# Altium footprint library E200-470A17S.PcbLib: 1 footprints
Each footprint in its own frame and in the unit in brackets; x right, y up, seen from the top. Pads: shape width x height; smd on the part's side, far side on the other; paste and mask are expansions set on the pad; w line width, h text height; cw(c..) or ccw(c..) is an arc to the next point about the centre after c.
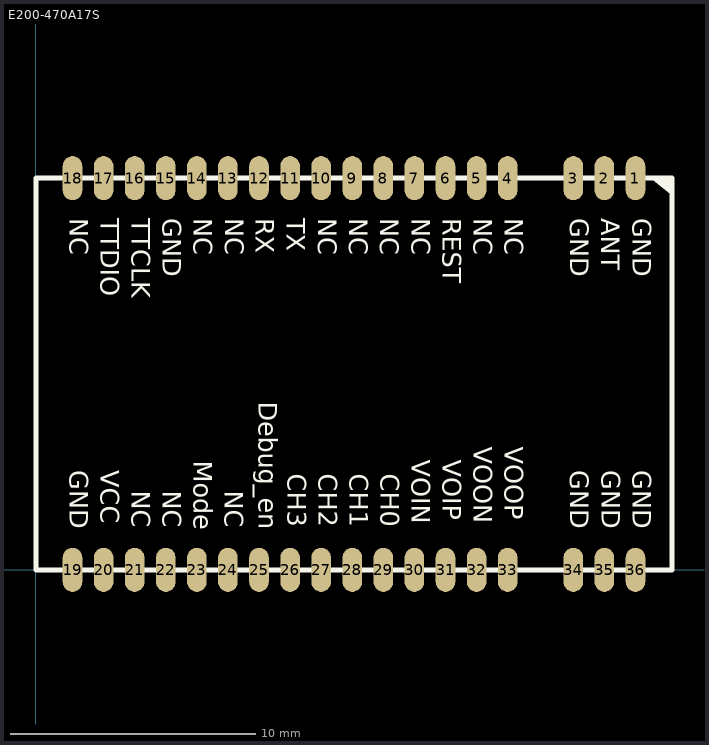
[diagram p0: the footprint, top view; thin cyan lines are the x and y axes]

## E200-470A17S [mm] "26*16mm"
pads (36):
  oval 0.8x1.8 smd: 1(24.5,16) 2(23.23,16) 3(21.96,16) 4(19.28,16) 5(18.01,16) 6(16.74,16) 7(15.47,16) 8(14.2,16) 9(12.93,16) 10(11.66,16) 11(10.39,16) 12(9.12,16) 13(7.85,16) 14(6.58,16) 15(5.31,16) 16(4.04,16) 17(2.77,16) 18(1.5,16) 19(1.5,0) 20(2.77,0) 21(4.04,0) 22(5.31,0) 23(6.58,0) 24(7.85,0) 25(9.12,0) 26(10.39,0) 27(11.66,0) 28(12.93,0) 29(14.2,0) 30(15.47,0) 31(16.74,0) 32(18.01,0) 33(19.28,0) 34(21.96,0) 35(23.23,0) 36(24.5,0)
Top Overlay:
  region: 25.283,15.994 25.289,16 26,16 26,15.417 25.99,15.407
  lines w0.2: 25.283,15.994 25.99,15.407 ; 0,0 0,16 26,16 26,0 0,0
  text "VOIP" at 16.364,4.488 h1.3
  text "Debug_en" at 8.841,6.862 h1.3
  text "NC" at 7.463,3.238 h1.3
  text "Mode" at 6.192,4.458 h1.3
  text "NC" at 3.653,3.238 h1.3
  text "GND" at 24.119,4.064 h1.3
  text "GND" at 22.849,4.064 h1.3
  text "GND" at 21.579,4.064 h1.3
  text "REST" at 16.356,14.369 h1.3
  text "NC" at 17.626,14.369 h1.3
  text "NC" at 18.896,14.369 h1.3
  text "RX" at 8.721,14.369 h1.3
  text "NC" at 7.466,14.369 h1.3
  text "NC" at 6.196,14.369 h1.3
  text "GND" at 24.116,14.369 h1.3
  text "ANT" at 22.831,14.369 h1.3
  text "GND" at 21.576,14.369 h1.3
  text "NC" at 1.116,14.369 h1.3
  text "TTDIO" at 2.386,14.369 h1.3
  text "TTCLK" at 3.656,14.369 h1.3
  text "GND" at 4.926,14.369 h1.3
  text "NC" at 15.086,14.369 h1.3
  text "NC" at 13.816,14.369 h1.3
  text "NC" at 12.546,14.369 h1.3
  text "NC" at 11.276,14.369 h1.3
  text "TX" at 9.991,14.369 h1.3
  text "GND" at 1.119,4.064 h1.3
  text "VCC" at 2.389,4.062 h1.3
  text "NC" at 4.923,3.238 h1.3
  text "CH0" at 13.833,3.918 h1.3
  text "VOIN" at 15.094,4.488 h1.3
  text "VOON" at 17.623,5.023 h1.3
  text "VOOP" at 18.893,5.023 h1.3
  text "CH1" at 12.563,3.918 h1.3
  text "CH2" at 11.293,3.918 h1.3
  text "CH3" at 10.023,3.918 h1.3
